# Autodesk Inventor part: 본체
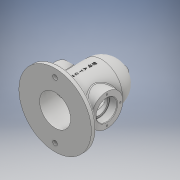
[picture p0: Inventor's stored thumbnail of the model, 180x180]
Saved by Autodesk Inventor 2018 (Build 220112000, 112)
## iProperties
Created: 2019-11
Part Number: 본체
Material: Generic
Document SubType Name: Modeling
Designer: Administrator
Density: 1 g/cm^3
Appearance: Default
Author: Administrator
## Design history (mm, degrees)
sketch "스케치1"
  geometry: C1 r 40 at (0, 0); 1 further point
  constraints: 1 centre point, 1 coincident
  dimensions: "d0" = 80 diameter of C1
extrude "돌출1" new body sketch "스케치1" stored distance "d1" = 80; taper "d2" = 0 deg
sketch "스케치2"
  geometry: C1 r 70 at (0, 0); 1 further point
  constraints: 1 centre point, 1 coincident
  dimensions: "d3" = 140 diameter of C1
extrude "돌출2" join sketch "스케치2" distance "d4" = 10; taper "d5" = 0 deg
sketch "스케치3"
  geometry: L1 (0, 40)-(2.348, 40); L2 (2.348, 40)-(40, 40); L3 (0, 40)-(0, 80); L4 (40, 40)-(-40, 40) reference; L5 (0, 83.321)-(0, 31.189); A1 r 40 centre (0, 40) between (40, 40) and (0, 80); 1 further point
  constraints: 8 end point, 2 point on circle, 1 centre point, 1 collinear, 1 perpendicular, 1 vertical
revolve "회전1" sketch "스케치3" stored, may be unused: angle "d6" = 90 deg
sketch "스케치4"
  geometry: L1 (-50, 70)-(-50, -70) reference; L2 (-50, 0)-(0, 0); C1 r 31 at (0, 0)
  constraints: 2 end point, 1 centre point, 1 coincident, 1 horizontal, 1 midpoint
  dimensions: "d7" = 50 distance of L2.start L2.end (derived); "d8" = 62 diameter of C1
extrude "돌출3" join sketch "스케치4" stored distance "d9" = 100; taper "d10" = 0 deg
sketch "스케치5"
  geometry: C1 r 30 at (0, 0); 1 further point
  constraints: 1 centre point, 1 coincident
  dimensions: "d11" = 60 diameter of C1
extrude "돌출4" cut sketch "스케치5" distance "d12" = 90; taper "d13" = 0 deg
sketch "스케치6"
  geometry: L1 (30, 40)-(-30, 40) reference; L2 (0, 40)-(0, 70); L3 (30, 40)-(0, 40); L4 (0, 73.114)-(0, 27.155); A1 r 30 centre (0, 40) between (30, 40) and (0, 70); 1 further point
  constraints: 7 end point, 3 point on circle, 2 vertical, 1 centre point, 1 coincident, 1 collinear, 1 midpoint, 1 point on line
revolve "회전2" sketch "스케치6" stored, may be unused: angle "d15" = 90 deg
sketch "스케치7"
  geometry: C1 r 16.5 at (0, 0); 1 further point
  constraints: 1 centre point, 1 coincident
  dimensions: "d16" = 33 diameter of C1
extrude "돌출5" cut sketch "스케치7" distance "d17" = 100; taper "d18" = 0 deg
sketch "스케치8"
  geometry: C1 r 20 at (0, 0); 1 further point
  constraints: 1 centre point, 1 coincident
  dimensions: "d19" = 40 diameter of C1
extrude "돌출6" cut sketch "스케치8" distance "d20" = 15; taper "d21" = 0 deg
sketch "스케치9"
  geometry: L1 (0, 0)-(0, 85)
  constraints: 2 end point, 1 vertical
  dimensions: "d22" = 85 distance of L1.start L1.end
node "작업 평면1"
sketch "스케치10"
  geometry: C1 r 7.5 at (0, 0); 1 further point
  constraints: 1 centre point, 1 coincident
  dimensions: "d23" = 15 diameter of C1
extrude "돌출7" join sketch "스케치10" stored distance "d24" = 15; taper "d25" = 0 deg
sketch "스케치11"
  geometry: C1 r 4.5 at (0, 55); C2 r 4.5 at (0, -55); 1 further point
  constraints: 2 centre point
  dimensions: "d27" = 9 diameter of C1; "d28" = 9 diameter of C2
extrude "돌출8" cut sketch "스케치11" distance "d29" = 15; taper "d30" = 0 deg
sketch "스케치12"
  geometry: 2 further points
  constraints: 1 coincident
hole "구멍1" sketch "스케치12" at (0, 0) diameter "d31" = 4.917; stored, may be unused: countersink angle "d35" = 90 deg, drill point angle "d37" = 118 deg; dims "d32" = 12, "d33" = 4, "d34" = 2, "d36" = 17.1
sketch "스케치13"
  geometry: A1 r 26 centre (0, 0) between (0, 26) and (-26, 0); 3 further points
  constraints: 4 point on circle, 1 centre point, 1 coincident
  dimensions: "d38" = 52 diameter of A1
hole "구멍2" sketch "스케치13" at (0, 26), (-26, 0), (0, -26), (26, 0) diameter "d39" = 3.242; stored, may be unused: countersink angle "d43" = 90 deg, drill point angle "d45" = 118 deg; dims "d40" = 8, "d41" = 4, "d42" = 2, "d44" = 10
sketch "스케치14"
  geometry: L1 (-50, 70)-(-50, -70) reference; L2 (0, 70)-(0, 78.186); 1 further point
  constraints: 2 end point
node "작업 평면2"
sketch "스케치15"
  geometry: L1 (-3.474, 28.821)-(3.474, 28.821); L2 (3.474, 28.821)-(3.474, -28.821); L3 (3.474, -28.821)-(-3.474, -28.821); L4 (-3.474, -28.821)-(-3.474, 28.821); L5 (-3.474, 0)-(3.474, 0); 2 further points
  constraints: 3 midpoint, 2 coincident, 2 end point, 2 other
feature "엠보싱1" sketch "스케치15" dims "d8" = 62, "d47" = 0.5, "d48" = 0
fillet "모깎기1" dims "d49" = 3
fillet "모깎기2" dims "d50" = 3
fillet "모깎기3" dims "d51" = 0.3
chamfer "모따기1" distance "d52" = 1; stored, may be unused: second distance "d53" = 2, angle "d54" = 45 deg
node "솔리드1"
mirror "미러1"
mirror "미러2"
